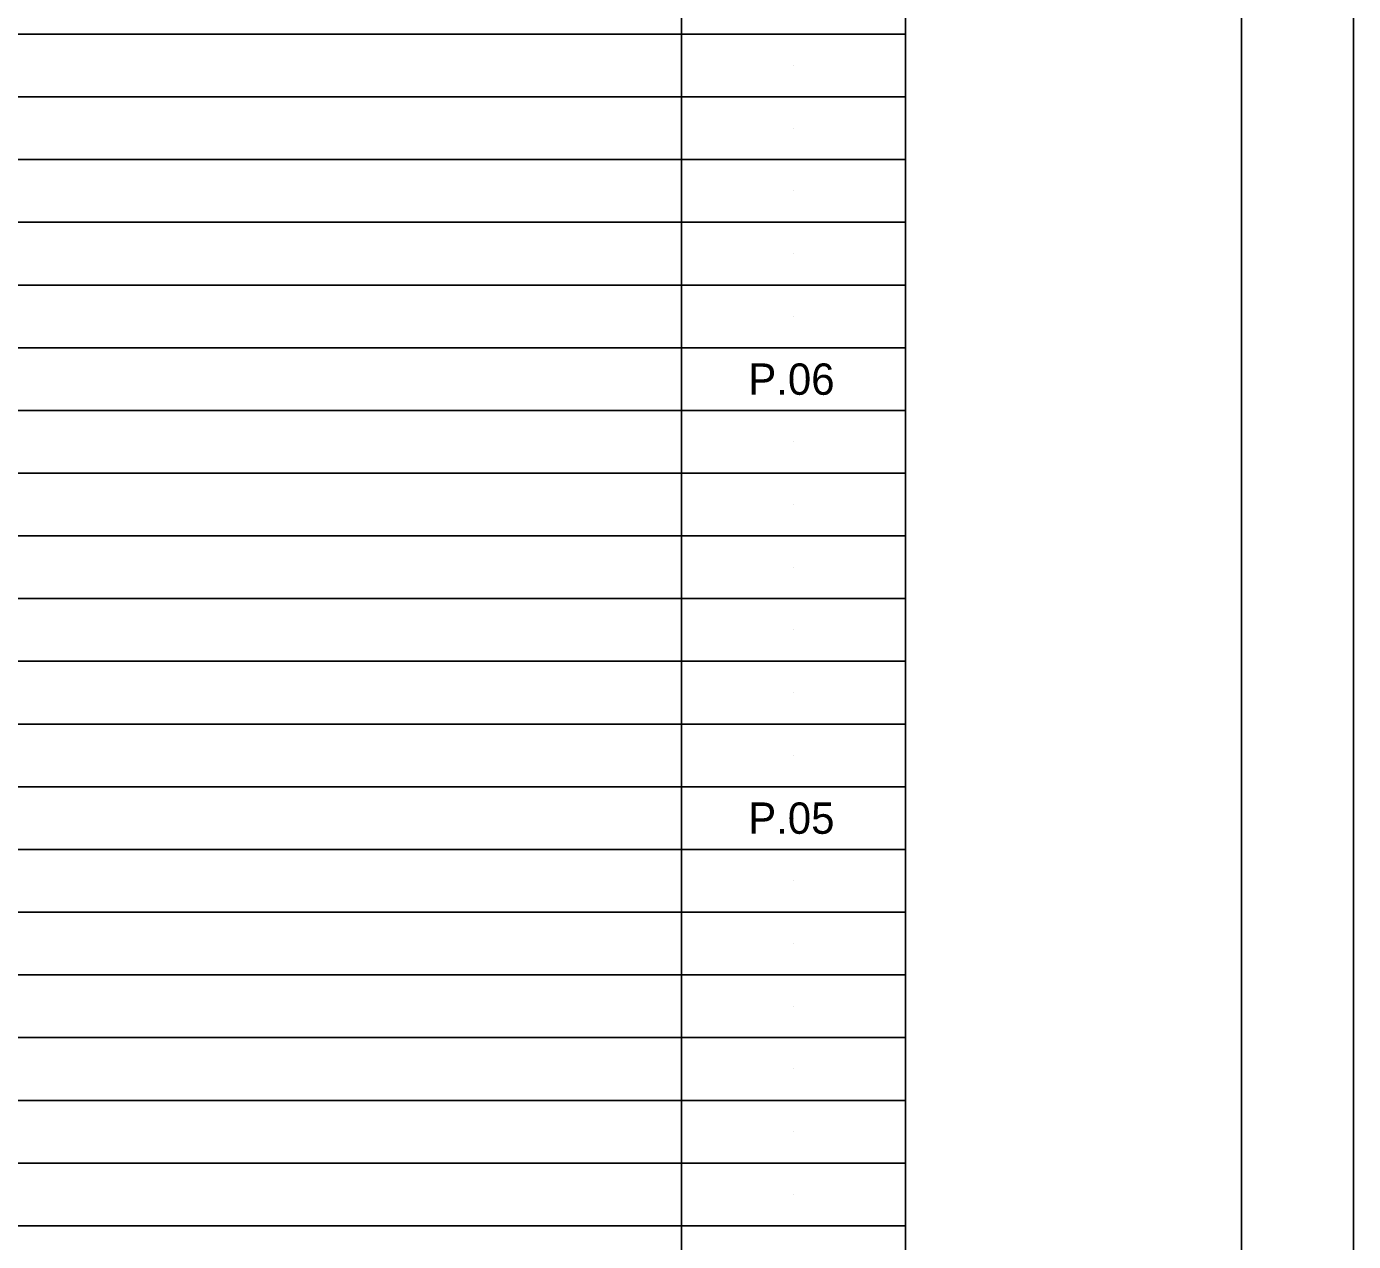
# Model space of a CAD drawing. Extents: x 0 to 34, y 0 to 22.
# Drawn here: x 28.07 to 34, y 5.47 to 10.89 of the extents above; entities that cross this region are included whole.
import ezdxf

# ---------------------------------------------------------------- set-up
doc = ezdxf.new("R2010")
doc.units = 0
for name, color, linetype in [('RD_P_Text', 7, 'Continuous'), ('SC_Scratch1', 7, 'Continuous'), ('SH_Border', 7, 'Continuous'), ('SH_Cut_Line', 7, 'Continuous'), ('SH_Data', 7, 'Continuous')]:
    doc.layers.add(name, color=color, linetype=linetype)

msp = doc.modelspace()

# ---------------------------------------------------------------- linework, layer by layer
at = {"layer": 'SC_Scratch1'}
for p, q in [((31.5, 10.72), (31.5, 10.72)), ((31.5, 10.44), (31.5, 10.44)), ((31.5, 10.16), (31.5, 10.16)), ((31.5, 9.88), (31.5, 9.88)), ((31.5, 9.6), (31.5, 9.6)), ((31.5, 9.32), (31.5, 9.32)), ((31.5, 9.04), (31.5, 9.04)), ((31.5, 8.76), (31.5, 8.76)), ((31.5, 8.48), (31.5, 8.48)), ((31.5, 8.2), (31.5, 8.2)), ((31.5, 7.92), (31.5, 7.92)), ((31.5, 7.64), (31.5, 7.64)), ((31.5, 7.36), (31.5, 7.36)), ((31.5, 7.08), (31.5, 7.08)), ((31.5, 6.8), (31.5, 6.8)), ((31.5, 6.52), (31.5, 6.52)), ((31.5, 6.24), (31.5, 6.24)), ((31.5, 5.96), (31.5, 5.96)), ((31.5, 5.68), (31.5, 5.68))]:
    msp.add_line(p, q, dxfattribs=at)
at = {"layer": 'SH_Border'}
msp.add_line((32, 0.5), (32, 21.5), dxfattribs=at)
msp.add_lwpolyline([(1.5, 21.5), (33.5, 21.5), (33.5, 0.5), (1.5, 0.5)], close=True, dxfattribs=at)
at = {"layer": 'SH_Cut_Line'}
msp.add_lwpolyline([(0, 0), (34, 0), (34, 22), (0, 22)], close=True, dxfattribs=at)
at = {"layer": 'SH_Data'}
for p, q in [((31, 21.5), (31, 0.5)), ((32, 10.86), (1.5, 10.86)), ((32, 10.58), (1.5, 10.58)), ((32, 10.3), (1.5, 10.3)), ((32, 10.02), (1.5, 10.02)), ((32, 9.74), (1.5, 9.74)), ((32, 9.46), (1.5, 9.46)), ((32, 9.18), (1.5, 9.18)), ((32, 8.9), (1.5, 8.9)), ((32, 8.62), (1.5, 8.62)), ((32, 8.34), (1.5, 8.34)), ((32, 8.06), (1.5, 8.06)), ((32, 7.78), (1.5, 7.78)), ((32, 7.5), (1.5, 7.5)), ((32, 7.22), (1.5, 7.22)), ((32, 6.94), (1.5, 6.94)), ((32, 6.66), (1.5, 6.66)), ((32, 6.38), (1.5, 6.38)), ((32, 6.1), (1.5, 6.1)), ((32, 5.82), (1.5, 5.82)), ((32, 5.54), (1.5, 5.54))]:
    msp.add_line(p, q, dxfattribs=at)

# ---------------------------------------------------------------- texts
at = {"layer": 'RD_P_Text'}
for s, p in [('P.06', (31.2977, 9.25)), ('P.05', (31.2973, 7.29))]:
    msp.add_text(s, height=0.14, dxfattribs=at).set_placement(p)

doc.saveas('drawing.dxf')
